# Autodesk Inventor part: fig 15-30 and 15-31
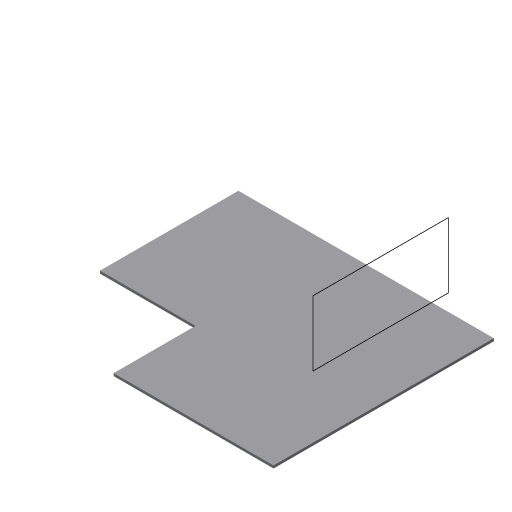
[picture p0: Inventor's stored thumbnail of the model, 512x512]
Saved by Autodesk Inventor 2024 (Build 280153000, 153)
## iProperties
Created: 2005-03
Part Number: fig 15-30 and 15-31
Document SubType Name: Sheet Metal
Designer: CADCIM
Manufacturer: Standard
Standards Organization: Custom
Density: 1 g/cm^3
Sheet Metal Rule: Default
Material: Generic
Appearance: Default
Author: CADCIM
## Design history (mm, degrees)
node "Face1"
  sketch "Sketch1"
    geometry: L1 (29.25, 32.25)-(-19.875, 32.25); L2 (-19.875, 32.25)-(-19.875, 5.625); L3 (-19.875, 5.625)-(-1.5, 5.625); L4 (-1.5, 5.625)-(-1.5, -10.125); L5 (-1.5, -10.125)-(29.25, -10.125); L6 (29.25, -10.125)-(29.25, 32.25)
    constraints: 12 end point, 4 parallel, 1 horizontal, 1 perpendicular
sketch "Sketch2"
  geometry: L1 (-12.475, 7.526)-(-25.013, 7.526); L2 (-25.013, 7.526)-(-25.013, 33.56); L3 (-25.013, 33.56)-(-12.475, 33.56); L4 (-12.475, 33.56)-(-12.475, 7.526)
  constraints: 8 end point, 2 parallel, 1 horizontal, 1 perpendicular
body "Solid1"
face "Plate1" dims "d1" = 0.5 (= Thickness)
other parameters: "Thickness" = 0.5, "BendRadius" = 0.5 (= Thickness), "BendReliefWidth" = 0.5 (= Thickness), "BendReliefDepth" = 0.25 (= 0.5 x Thickness), "CornerReliefSize" = 2 (= 4 x Thickness), "SeamGap" = 0.01, "MinimumRemnant" = 1 (= 2 x Thickness), "TransitionRadius" = 0.5 (= BendRadius), "d0" = 0.5 (= BendRadius), "JacobiRadiusSize" = 0.5 (= Thickness), "GapSize" = 0.5 (= Thickness)
